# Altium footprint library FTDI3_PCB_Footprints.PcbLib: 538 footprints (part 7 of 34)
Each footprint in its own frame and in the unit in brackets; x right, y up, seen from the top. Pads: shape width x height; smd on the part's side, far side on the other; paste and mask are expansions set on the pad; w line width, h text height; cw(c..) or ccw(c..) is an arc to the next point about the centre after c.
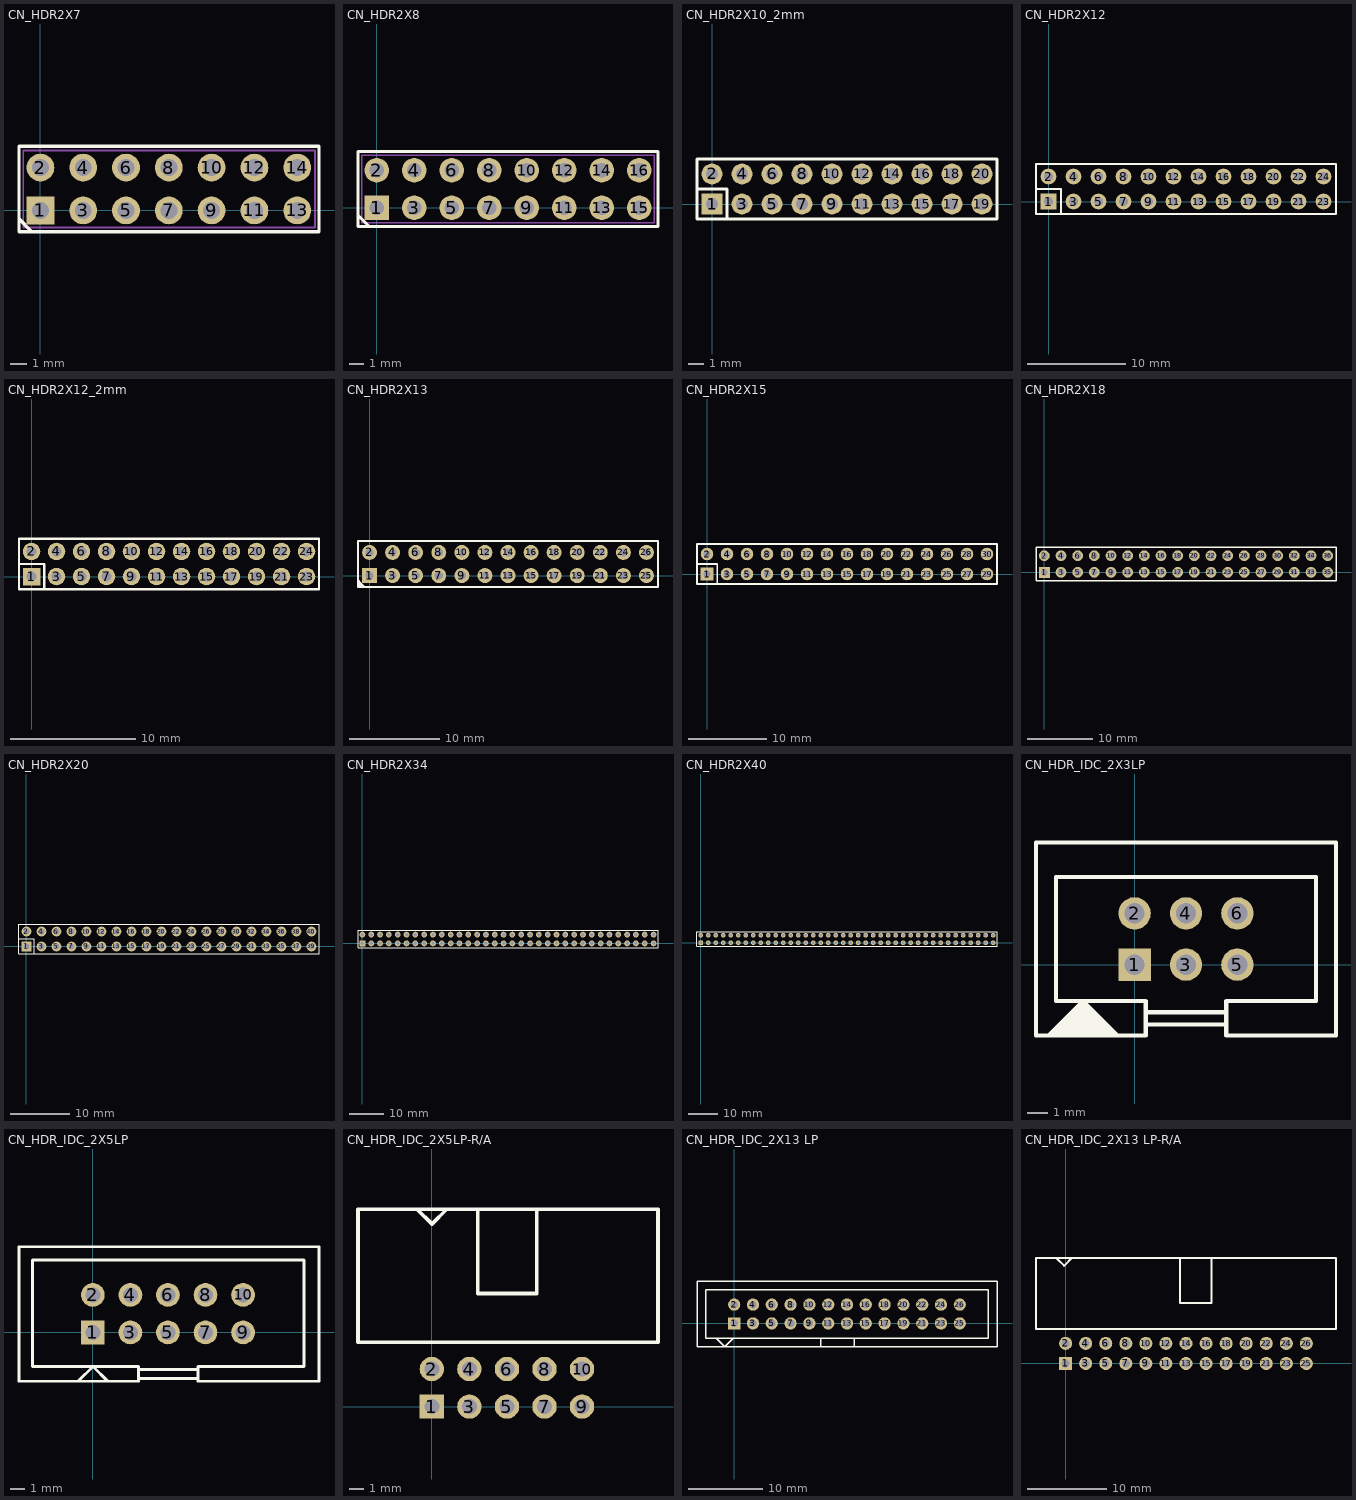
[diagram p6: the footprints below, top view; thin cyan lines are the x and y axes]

## CN_HDR2X7 [mil] "Connector; Header; 7x2 Position; pitch 0.1\""
pads (14):
  rect 65x65 hole 39.37: 1(0,0)
  round 65 hole 39.37: 2(0,100) 3(100,0) 4(100,100) 5(200,0) 6(200,100) 7(300,0) 8(300,100) 9(400,0) 10(400,100) 11(500,0) 12(500,100) 13(600,0) 14(600,100)
Top Overlay:
  lines w7.87: -50,-19.88 -19.88,-50 ; -50,-50 650.79,-50 650.79,150 -50,150 -50,-50
M7_3D_Body:
  lines w3.94: -40,-40 -40,140 641.34,140 641.34,-40 -40,-40

## CN_HDR2X8 [mil] "Connector; Header; 8x2 Position; pitch 0.1\""
pads (16):
  rect 65x65 hole 39.37: 1(0,0)
  round 65 hole 39.37: 2(0,100) 3(100,0) 4(100,100) 5(200,0) 6(200,100) 7(300,0) 8(300,100) 9(400,0) 10(400,100) 11(500,0) 12(500,100) 13(600,0) 14(600,100) 15(700,0) 16(700,100)
Top Overlay:
  lines w7.87: -50,-19.88 -19.88,-50 ; -50,-50 -50,150 750,150 750,-50 -50,-50
M7_3D_Body:
  lines w3.94: -40,-40 740,-40 740,140 -40,140 -40,-40

## CN_HDR2X10_2mm [mm] "Connector; Header; 2 Rows x 10 Positions; pitch 2.0mm"
pads (20):
  rect 1.4x1.4 hole 0.8: 1(0,0)
  round 1.4 hole 0.8: 2(0,2) 3(2,0) 4(2,2) 5(4,0) 6(4,2) 7(6,0) 8(6,2) 9(8,0) 10(8,2) 11(10,0) 12(10,2) 13(12,0) 14(12,2) 15(14,0) 16(14,2) 17(16,0) 18(16,2) 19(18,0) 20(18,2)
Top Overlay:
  lines w0.2: 1,-1 1,1 -1,1 ; -1,1 -1,-1 19,-1 19,1 19,3 -1,3 -1,1

## CN_HDR2X12 [mm] "Connector; Header; Female; 2x12 Position; Pitch 0.1\""
pads (24):
  rect 1.6x1.6 hole 0.9: 1(0,0)
  round 1.6 hole 0.9: 2(0,2.54) 3(2.54,0) 4(2.54,2.54) 5(5.08,0) 6(5.08,2.54) 7(7.62,0) 8(7.62,2.54) 9(10.16,0) 10(10.16,2.54) 11(12.7,0) 12(12.7,2.54) 13(15.24,0) 14(15.24,2.54) 15(17.78,0) 16(17.78,2.54) 17(20.32,0) 18(20.32,2.54) 19(22.86,0) 20(22.86,2.54) 21(25.4,0) 22(25.4,2.54) 23(27.94,0) 24(27.94,2.54)
Top Overlay:
  lines w0.2: -1.265,1.27 1.275,1.27 1.275,-1.27 ; -1.27,-1.27 -1.27,3.81 29.21,3.81 29.21,-1.27 -1.27,-1.27

## CN_HDR2X12_2mm [mm] "Connector; Header; 2 Rows x 12 Positions; pitch 2.0mm"
height 4.5
pads (24):
  rect 1.4x1.4 hole 0.8: 1(0,0)
  round 1.4 hole 0.8: 2(0,2) 3(2,0) 4(2,2) 5(4,0) 6(4,2) 7(6,0) 8(6,2) 9(8,0) 10(8,2) 11(10,0) 12(10,2) 13(12,0) 14(12,2) 15(14,0) 16(14,2) 17(16,0) 18(16,2) 19(18,0) 20(18,2) 21(20,0) 22(20,2) 23(22,0) 24(22,2)
Top Overlay:
  lines w0.2: 1,-1 1,1 -1,1 ; -1,1 -1,-1 23,-1 23,3 -1,3 -1,1

## CN_HDR2X13 [mil] "Connector; Header; Male; 13x2 Position; Pitch 0.1\""
pads (26):
  rect 65x65 hole 35.43: 1(0,0)
  round 65 hole 35.43: 2(0,100) 3(100,0) 4(100,100) 5(200,0) 6(200,100) 7(300,0) 8(300,100) 9(400,0) 10(400,100) 11(500,0) 12(500,100) 13(600,0) 14(600,100) 15(700,0) 16(700,100) 17(800,0) 18(800,100) 19(900,0) 20(900,100) 21(1000,0) 22(1000,100) 23(1100,0) 24(1100,100) 25(1200,0) 26(1200,100)
Top Overlay:
  region: -50,-50 -50,-15.35 -32.68,-32.68 -15.35,-50
  lines w7.87: -50,-50 1250,-50 1250,150 -50,150 -50,-50

## CN_HDR2X15 [mm] "Connector; Header; Female; 15x2 Position; Pitch 0.1\""
pads (30):
  rect 1.6x1.6 hole 0.9: 1(0,0)
  round 1.6 hole 0.9: 2(0,2.54) 3(2.54,0) 4(2.54,2.54) 5(5.08,0) 6(5.08,2.54) 7(7.62,0) 8(7.62,2.54) 9(10.16,0) 10(10.16,2.54) 11(12.7,0) 12(12.7,2.54) 13(15.24,0) 14(15.24,2.54) 15(17.78,0) 16(17.78,2.54) 17(20.32,0) 18(20.32,2.54) 19(22.86,0) 20(22.86,2.54) 21(25.4,0) 22(25.4,2.54) 23(27.94,0) 24(27.94,2.54) 25(30.48,0) 26(30.48,2.54) 27(33.02,0) 28(33.02,2.54) 29(35.56,0) 30(35.56,2.54)
Top Overlay:
  lines w0.2: -1.265,1.27 1.275,1.27 1.275,-1.27 ; -1.27,-1.27 -1.27,3.81 36.83,3.81 36.83,-1.27 -1.27,-1.27

## CN_HDR2X18 [mil] "Connector; Header; 18x2 Position; Pitch 0.1\""
pads (36):
  rect 65x65 hole 39.37: 1(0,0)
  round 65 hole 39.37: 2(0,100) 3(100,0) 4(100,100) 5(200,0) 6(200,100) 7(300,0) 8(300,100) 9(400,0) 10(400,100) 11(500,0) 12(500,100) 13(600,0) 14(600,100) 15(700,0) 16(700,100) 17(800,0) 18(800,100) 19(900,0) 20(900,100) 21(1000,0) 22(1000,100) 23(1100,0) 24(1100,100) 25(1200,0) 26(1200,100) 27(1300,0) 28(1300,100) 29(1400,0) 30(1400,100) 31(1500,0) 32(1500,100) 33(1600,0) 34(1600,100) 35(1700,0) 36(1700,100)
Top Overlay:
  lines w7.87: -50,-50 1750,-50 1750,150 -50,150 -50,-50

## CN_HDR2X20 [mil] "Connector; Header; Male; 2x20 Positions; Pitch 0.1\""
height 329.92
pads (40):
  rect 65x65 hole 39.37: 1(0,0)
  round 65 hole 39.37: 2(0,100) 3(100,0) 4(100,100) 5(200,0) 6(200,100) 7(300,0) 8(300,100) 9(400,0) 10(400,100) 11(500,0) 12(500,100) 13(600,0) 14(600,100) 15(700,0) 16(700,100) 17(800,0) 18(800,100) 19(900,0) 20(900,100) 21(1000,0) 22(1000,100) 23(1100,0) 24(1100,100) 25(1200,0) 26(1200,100) 27(1300,0) 28(1300,100) 29(1400,0) 30(1400,100) 31(1500,0) 32(1500,100) 33(1600,0) 34(1600,100) 35(1700,0) 36(1700,100) 37(1800,0) 38(1800,100) 39(1900,0) 40(1900,100)
Top Overlay:
  lines w7.87: -50,51.18 51.18,51.18 51.18,-50 ; -50,-50 -50,150 1750,150 1950.39,150 1950.39,-50 1750,-50 -50,-50

## CN_HDR2X34 [mil] "Connector; Header; Male; 2x34 Positions; Pitch 0.1\""
height 329.92
pads (68):
  rect 65x65 hole 39.37: 1(0,0)
  round 65 hole 39.37: 2(0,100) 3(100,0) 4(100,100) 5(200,0) 6(200,100) 7(300,0) 8(300,100) 9(400,0) 10(400,100) 11(500,0) 12(500,100) 13(600,0) 14(600,100) 15(700,0) 16(700,100) 17(800,0) 18(800,100) 19(900,0) 20(900,100) 21(1000,0) 22(1000,100) 23(1100,0) 24(1100,100) 25(1200,0) 26(1200,100) 27(1300,0) 28(1300,100) 29(1400,0) 30(1400,100) 31(1500,0) 32(1500,100) 33(1600,0) 34(1600,100) 35(1700,0) 36(1700,100) 37(1800,0) 38(1800,100) 39(1900,0) 40(1900,100) 41(2000,0) 42(2000,100) 43(2100,0) 44(2100,100) 45(2200,0) 46(2200,100) 47(2300,0) 48(2300,100) 49(2400,0) 50(2400,100) 51(2500,0) 52(2500,100) 53(2600,0) 54(2600,100) 55(2700,0) 56(2700,100) 57(2800,0) 58(2800,100) 59(2900,0) 60(2900,100) 61(3000,0) 62(3000,100) 63(3100,0) 64(3100,100) 65(3200,0) 66(3200,100) 67(3300,0) 68(3300,100)
Top Overlay:
  lines w7.87: -50,-50 1750,-50 3350.39,-50 3350.39,150 1750,150 -50,150 -50,-50

## CN_HDR2X40 [mil] "Connector; Header; Male; 2x80 Positions; Pitch 0.1\""
height 329.92
pads (80):
  rect 65x65 hole 39.37: 1(0,0)
  round 65 hole 39.37: 2(0,100) 3(100,0) 4(100,100) 5(200,0) 6(200,100) 7(300,0) 8(300,100) 9(400,0) 10(400,100) 11(500,0) 12(500,100) 13(600,0) 14(600,100) 15(700,0) 16(700,100) 17(800,0) 18(800,100) 19(900,0) 20(900,100) 21(1000,0) 22(1000,100) 23(1100,0) 24(1100,100) 25(1200,0) 26(1200,100) 27(1300,0) 28(1300,100) 29(1400,0) 30(1400,100) 31(1500,0) 32(1500,100) 33(1600,0) 34(1600,100) 35(1700,0) 36(1700,100) 37(1800,0) 38(1800,100) 39(1900,0) 40(1900,100) 41(2000,0) 42(2000,100) 43(2100,0) 44(2100,100) 45(2200,0) 46(2200,100) 47(2300,0) 48(2300,100) 49(2400,0) 50(2400,100) 51(2500,0) 52(2500,100) 53(2600,0) 54(2600,100) 55(2700,0) 56(2700,100) 57(2800,0) 58(2800,100) 59(2900,0) 60(2900,100) 61(3000,0) 62(3000,100) 63(3100,0) 64(3100,100) 65(3200,0) 66(3200,100) 67(3300,0) 68(3300,100) 69(3400,0) 70(3400,100) 71(3500,0) 72(3500,100) 73(3600,0) 74(3600,100) 75(3700,0) 76(3700,100) 77(3800,0) 78(3800,100) 79(3900,0) 80(3900,100)
Top Overlay:
  lines w7.87: -50,-50 -50,150 1750,150 3950.39,150 3950.39,-50 1750,-50 -50,-50

## CN_HDR_IDC_2X3LP [mm] "Connector; Header; Lo Profile; 2x3 Position; Pitch 0.1\""
height 9.57
pads (6):
  rect 1.6x1.6 hole 1: 1(0,0)
  round 1.6 hole 1: 2(0,2.54) 3(2.54,0) 4(2.54,2.54) 5(5.08,0) 6(5.08,2.54)
Top Overlay:
  region: -2.55,-1.805 -4.25,-3.505 -0.85,-3.505
  lines w0.2: -4.25,-3.505 -2.55,-1.805 -0.85,-3.505 ; 0.55,-2.95 4.53,-2.95 ; 0.55,-2.35 4.53,-2.35 ; -4.875,-3.505 0.55,-3.505 0.55,-1.805 -3.885,-1.805 -3.885,4.345 8.965,4.345 8.965,-1.805 4.53,-1.805 4.53,-3.505 9.955,-3.505 9.955,6.045 -4.875,6.045 -4.875,-3.505

## CN_HDR_IDC_2X5LP [mm] "Connector; Header; Lo Profile; 5x2 Position; Pitch 0.1\""
pads (10):
  rect 1.6x1.6 hole 1: 1(0,0)
  round 1.6 hole 1: 2(0,2.54) 3(2.54,0) 4(2.54,2.54) 5(5.08,0) 6(5.08,2.54) 7(7.62,0) 8(7.62,2.54) 9(10.16,0) 10(10.16,2.54)
Top Overlay:
  lines w0.2: -1,-3.3 0,-2.3 1,-3.3 ; 3.1,-3.1 7.1,-3.1 ; 3.1,-2.5 7.1,-2.5 ; -5,-3.3 -5,5.8 15.3,5.8 15.3,-3.3 7.1,-3.3 7.1,-2.3 14.3,-2.3 14.3,4.9 -4.1,4.9 -4.1,-2.3 3.1,-2.3 3.1,-3.3 -5,-3.3

## CN_HDR_IDC_2X5LP-R/A [mil] "Connector; Header; Horizontal; Lo Profile; 5x2 Position; Pitch 0.1\""
pads (10):
  rect 65x65 hole 39.37: 1(0,0)
  round 65 hole 39.37: 2(0,100) 3(100,0) 4(100,100) 5(200,0) 6(200,100) 7(300,0) 8(300,100) 9(400,0) 10(400,100)
Top Overlay:
  lines w10: -39.37,525.59 0,486.22 39.37,525.59 ; 122.05,525.59 122.05,301.18 279.53,301.18 279.53,525.59 ; -196.85,171.26 -196.85,525.59 602.36,525.59 602.36,171.26 -196.85,171.26
3D body: height 393.7, standoff 0, extent -196.85,171.26 602.36,525.59

## CN_HDR_IDC_2X13 LP [mil] "Connector; Header; Vertical; Low Profile; 2x13 Positions; Pitch 0.1\""
height 358.27
pads (26):
  rect 65x65 hole 39.37: 1(0,0)
  round 65 hole 39.37: 2(0,100) 3(100,0) 4(100,100) 5(200,0) 6(200,100) 7(300,0) 8(300,100) 9(400,0) 10(400,100) 11(500,0) 12(500,100) 13(600,0) 14(600,100) 15(700,0) 16(700,100) 17(800,0) 18(800,100) 19(900,0) 20(900,100) 21(1000,0) 22(1000,100) 23(1100,0) 24(1100,100) 25(1200,0) 26(1200,100)
Top Overlay:
  lines w7.87: -95.08,-78.15 -50,-123.23 -4.92,-78.15 ; 461.42,-123.23 461.42,-77.95 ; 638.58,-123.23 638.58,-77.95 ; -197.64,-123.23 -197.64,223.23 1397.64,223.23 1397.64,-123.23 -197.64,-123.23 ; -152.36,-77.95 1352.36,-77.95 1352.36,177.95 -152.36,177.95 -152.36,-77.95
3D body: height 358.27, standoff 0, extent -197.64,-123.23 1397.64,223.23

## CN_HDR_IDC_2X13 LP-R/A [mil] "Connector; Header; Horizontal; Low Profile; 2x13 Positions; Pitch 0.1\""
height 358.27
pads (26):
  rect 65x65 hole 39.37: 1(0,0)
  round 65 hole 39.37: 2(0,100) 3(100,0) 4(100,100) 5(200,0) 6(200,100) 7(300,0) 8(300,100) 9(400,0) 10(400,100) 11(500,0) 12(500,100) 13(600,0) 14(600,100) 15(700,0) 16(700,100) 17(800,0) 18(800,100) 19(900,0) 20(900,100) 21(1000,0) 22(1000,100) 23(1100,0) 24(1100,100) 25(1200,0) 26(1200,100)
Top Overlay:
  lines w7.87: 602.36,171.26 688.74,171.26
  lines w10: -47.24,525.59 -7.87,486.22 31.5,525.59 ; 569.29,525.59 569.29,301.18 726.77,301.18 726.77,525.59 ; -147.64,171.26 1347.64,171.26 1347.64,525.59 -147.64,525.59 -147.64,171.26
3D body: height 393.7, standoff 0, extent -147.64,171.26 1347.64,525.59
